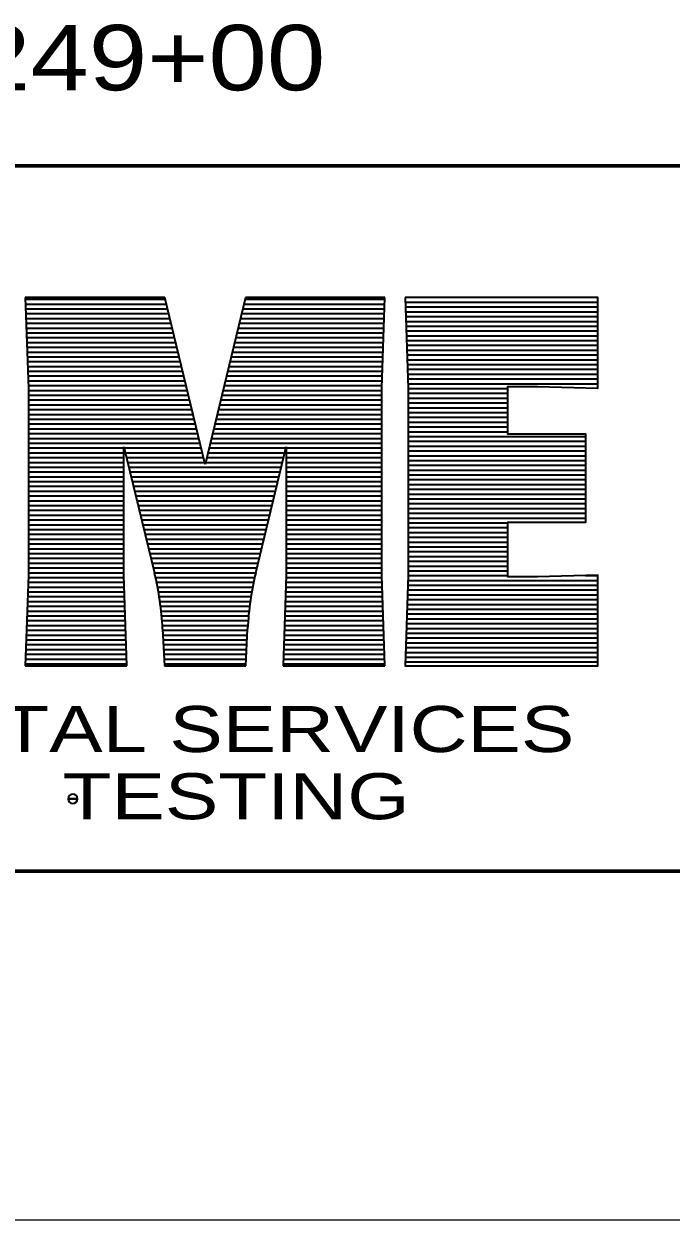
# Model space of a CAD drawing. Extents: x -76 to 974, y -1080 to -735.
# Drawn here: x 642.72 to 650.14, y -1056.11 to -1042.4 of the extents above; entities that cross this region are included whole.
import ezdxf
from ezdxf.enums import TextEntityAlignment as Align

# ---------------------------------------------------------------- set-up
doc = ezdxf.new("R2010")
doc.units = 0
doc.header["$LTSCALE"] = 0.36
doc.layers.add('63', color=7, linetype='Continuous', lineweight=35)

msp = doc.modelspace()

# ---------------------------------------------------------------- linework, layer by layer
at = {"layer": '63'}
for p, q in [((642.7326, -1045.5362), (642.7672, -1046.5743)), ((644.3305, -1045.5362), (642.7326, -1045.5362)), ((644.7933, -1047.4498), (644.3305, -1045.5362)), ((645.256, -1045.5362), (644.7933, -1047.4498)), ((646.8539, -1045.5362), (645.256, -1045.5362)), ((646.8193, -1046.5743), (646.8539, -1045.5362)), ((642.7332, -1045.5548), (644.335, -1045.5548)), ((642.7351, -1045.6098), (644.3483, -1045.6098)), ((642.7369, -1045.6648), (644.3616, -1045.6648)), ((645.2249, -1045.6648), (646.8496, -1045.6648)), ((645.2382, -1045.6098), (646.8514, -1045.6098)), ((645.2515, -1045.5548), (646.8533, -1045.5548)), ((647.0895, -1045.5883), (649.296, -1045.5883)), ((647.0913, -1045.6433), (649.296, -1045.6433)), ((642.7387, -1045.7198), (644.3749, -1045.7198)), ((642.7406, -1045.7748), (644.3882, -1045.7748)), ((645.1983, -1045.7748), (646.8459, -1045.7748)), ((645.2116, -1045.7198), (646.8478, -1045.7198)), ((647.0931, -1045.6983), (649.296, -1045.6983)), ((647.095, -1045.7533), (649.296, -1045.7533)), ((647.0968, -1045.8083), (649.296, -1045.8083)), ((642.7424, -1045.8298), (644.4015, -1045.8298)), ((642.7442, -1045.8848), (644.4148, -1045.8848)), ((642.7461, -1045.9398), (644.4281, -1045.9398)), ((645.1584, -1045.9398), (646.8404, -1045.9398)), ((645.1717, -1045.8848), (646.8423, -1045.8848)), ((645.185, -1045.8298), (646.8441, -1045.8298)), ((647.0986, -1045.8633), (649.296, -1045.8633)), ((647.1005, -1045.9183), (649.296, -1045.9183)), ((642.7479, -1045.9948), (644.4414, -1045.9948)), ((642.7497, -1046.0498), (644.4547, -1046.0498)), ((645.1318, -1046.0498), (646.8368, -1046.0498)), ((645.1451, -1045.9948), (646.8386, -1045.9948)), ((647.1023, -1045.9733), (649.296, -1045.9733)), ((647.1041, -1046.0283), (649.296, -1046.0283)), ((647.106, -1046.0833), (649.296, -1046.0833)), ((642.7516, -1046.1048), (644.468, -1046.1048)), ((642.7534, -1046.1598), (644.4813, -1046.1598)), ((642.7552, -1046.2148), (644.4946, -1046.2148)), ((645.0919, -1046.2148), (646.8313, -1046.2148)), ((645.1052, -1046.1598), (646.8331, -1046.1598)), ((645.1185, -1046.1048), (646.8349, -1046.1048)), ((647.1078, -1046.1383), (649.296, -1046.1383)), ((647.1096, -1046.1933), (649.296, -1046.1933)), ((642.7571, -1046.2698), (644.5079, -1046.2698)), ((642.7589, -1046.3248), (644.5212, -1046.3248)), ((645.0653, -1046.3248), (646.8276, -1046.3248)), ((645.0786, -1046.2698), (646.8294, -1046.2698)), ((647.1115, -1046.2483), (649.296, -1046.2483)), ((647.1133, -1046.3033), (649.296, -1046.3033)), ((647.1151, -1046.3583), (649.296, -1046.3583)), ((642.7607, -1046.3798), (644.5345, -1046.3798)), ((642.7626, -1046.4348), (644.5478, -1046.4348)), ((642.7644, -1046.4898), (644.5611, -1046.4898)), ((645.0254, -1046.4898), (646.8221, -1046.4898)), ((645.0387, -1046.4348), (646.8239, -1046.4348)), ((645.052, -1046.3798), (646.8258, -1046.3798)), ((647.117, -1046.4133), (649.296, -1046.4133)), ((647.1188, -1046.4683), (649.296, -1046.4683)), ((642.7662, -1046.5448), (644.5744, -1046.5448)), ((642.7672, -1046.5743), (642.7672, -1048.7197)), ((642.7672, -1046.5998), (644.5877, -1046.5998)), ((644.9988, -1046.5998), (646.8193, -1046.5998)), ((645.0121, -1046.5448), (646.8203, -1046.5448)), ((646.8193, -1048.7197), (646.8193, -1046.5743)), ((647.1206, -1046.5233), (649.296, -1046.5233)), ((647.1223, -1046.5783), (648.2643, -1046.5783)), ((647.1223, -1046.6333), (648.2643, -1046.6333)), ((642.7672, -1046.6548), (644.601, -1046.6548)), ((642.7672, -1046.7098), (644.6143, -1046.7098)), ((642.7672, -1046.7648), (644.6276, -1046.7648)), ((644.9589, -1046.7648), (646.8193, -1046.7648)), ((644.9722, -1046.7098), (646.8193, -1046.7098)), ((644.9855, -1046.6548), (646.8193, -1046.6548)), ((647.1223, -1046.6883), (648.2643, -1046.6883)), ((647.1223, -1046.7433), (648.2643, -1046.7433)), ((642.7672, -1046.8198), (644.6409, -1046.8198)), ((642.7672, -1046.8748), (644.6542, -1046.8748)), ((644.9323, -1046.8748), (646.8193, -1046.8748)), ((644.9456, -1046.8198), (646.8193, -1046.8198)), ((647.1223, -1046.7983), (648.2643, -1046.7983)), ((647.1223, -1046.8533), (648.2643, -1046.8533)), ((647.1223, -1046.9083), (648.2643, -1046.9083)), ((642.7672, -1046.9298), (644.6675, -1046.9298)), ((642.7672, -1046.9848), (644.6808, -1046.9848)), ((642.7672, -1047.0398), (644.6941, -1047.0398)), ((644.8924, -1047.0398), (646.8193, -1047.0398)), ((644.9057, -1046.9848), (646.8193, -1046.9848)), ((644.919, -1046.9298), (646.8193, -1046.9298)), ((647.1223, -1046.9633), (648.2643, -1046.9633)), ((647.1223, -1047.0183), (648.2643, -1047.0183)), ((642.7672, -1047.0948), (644.7074, -1047.0948)), ((642.7672, -1047.1498), (644.7207, -1047.1498)), ((644.8658, -1047.1498), (646.8193, -1047.1498)), ((644.8791, -1047.0948), (646.8193, -1047.0948)), ((647.1223, -1047.0733), (648.2643, -1047.0733)), ((647.1223, -1047.1283), (649.1571, -1047.1283)), ((647.1223, -1047.1833), (649.1571, -1047.1833)), ((642.7672, -1047.2048), (644.734, -1047.2048)), ((642.7672, -1047.2598), (643.8634, -1047.2598)), ((642.7672, -1047.3148), (643.8634, -1047.3148)), ((643.8634, -1047.2459), (644.2127, -1048.6901)), ((643.8634, -1048.7197), (643.8634, -1047.2459)), ((643.8668, -1047.2598), (644.7473, -1047.2598)), ((643.8801, -1047.3148), (644.7606, -1047.3148)), ((644.8259, -1047.3148), (645.7064, -1047.3148)), ((644.8392, -1047.2598), (645.7197, -1047.2598)), ((644.8525, -1047.2048), (646.8193, -1047.2048)), ((645.3738, -1048.6901), (645.7231, -1047.2459)), ((645.7231, -1047.2459), (645.7231, -1048.7197)), ((645.7231, -1047.2598), (646.8193, -1047.2598)), ((645.7231, -1047.3148), (646.8193, -1047.3148)), ((647.1223, -1047.2383), (649.1571, -1047.2383)), ((647.1223, -1047.2933), (649.1571, -1047.2933)), ((642.7672, -1047.3698), (643.8634, -1047.3698)), ((642.7672, -1047.4248), (643.8634, -1047.4248)), ((643.8934, -1047.3698), (644.7739, -1047.3698)), ((643.9067, -1047.4248), (644.7872, -1047.4248)), ((644.7993, -1047.4248), (645.6798, -1047.4248)), ((644.8126, -1047.3698), (645.6931, -1047.3698)), ((645.7231, -1047.3698), (646.8193, -1047.3698)), ((645.7231, -1047.4248), (646.8193, -1047.4248)), ((647.1223, -1047.3483), (649.1571, -1047.3483)), ((647.1223, -1047.4033), (649.1571, -1047.4033)), ((647.1223, -1047.4583), (649.1571, -1047.4583)), ((642.7672, -1047.4798), (643.8634, -1047.4798)), ((642.7672, -1047.5348), (643.8634, -1047.5348)), ((642.7672, -1047.5898), (643.8634, -1047.5898)), ((643.92, -1047.4798), (645.6665, -1047.4798)), ((643.9333, -1047.5348), (645.6532, -1047.5348)), ((643.9466, -1047.5898), (645.6399, -1047.5898)), ((645.7231, -1047.4798), (646.8193, -1047.4798)), ((645.7231, -1047.5348), (646.8193, -1047.5348)), ((645.7231, -1047.5898), (646.8193, -1047.5898)), ((647.1223, -1047.5133), (649.1571, -1047.5133)), ((647.1223, -1047.5683), (649.1571, -1047.5683)), ((642.7672, -1047.6448), (643.8634, -1047.6448)), ((642.7672, -1047.6998), (643.8634, -1047.6998)), ((643.9599, -1047.6448), (645.6266, -1047.6448)), ((643.9732, -1047.6998), (645.6133, -1047.6998)), ((645.7231, -1047.6448), (646.8193, -1047.6448)), ((645.7231, -1047.6998), (646.8193, -1047.6998)), ((647.1223, -1047.6233), (649.1571, -1047.6233)), ((647.1223, -1047.6783), (649.1571, -1047.6783)), ((647.1223, -1047.7333), (649.1571, -1047.7333)), ((642.7672, -1047.7548), (643.8634, -1047.7548)), ((642.7672, -1047.8098), (643.8634, -1047.8098)), ((642.7672, -1047.8648), (643.8634, -1047.8648)), ((643.9865, -1047.7548), (645.6, -1047.7548)), ((643.9998, -1047.8098), (645.5867, -1047.8098)), ((644.0131, -1047.8648), (645.5734, -1047.8648)), ((645.7231, -1047.7548), (646.8193, -1047.7548)), ((645.7231, -1047.8098), (646.8193, -1047.8098)), ((645.7231, -1047.8648), (646.8193, -1047.8648)), ((647.1223, -1047.7883), (649.1571, -1047.7883)), ((647.1223, -1047.8433), (649.1571, -1047.8433)), ((642.7672, -1047.9198), (643.8634, -1047.9198)), ((642.7672, -1047.9748), (643.8634, -1047.9748)), ((644.0264, -1047.9198), (645.5601, -1047.9198)), ((644.0397, -1047.9748), (645.5468, -1047.9748)), ((645.7231, -1047.9198), (646.8193, -1047.9198)), ((645.7231, -1047.9748), (646.8193, -1047.9748)), ((647.1223, -1047.8983), (649.1571, -1047.8983)), ((647.1223, -1047.9533), (649.1571, -1047.9533)), ((647.1223, -1048.0083), (649.1571, -1048.0083)), ((642.7672, -1048.0298), (643.8634, -1048.0298)), ((642.7672, -1048.0848), (643.8634, -1048.0848)), ((642.7672, -1048.1398), (643.8634, -1048.1398)), ((644.053, -1048.0298), (645.5335, -1048.0298)), ((644.0663, -1048.0848), (645.5202, -1048.0848)), ((644.0796, -1048.1398), (645.5069, -1048.1398)), ((645.7231, -1048.0298), (646.8193, -1048.0298)), ((645.7231, -1048.0848), (646.8193, -1048.0848)), ((645.7231, -1048.1398), (646.8193, -1048.1398)), ((647.1223, -1048.0633), (649.1571, -1048.0633)), ((647.1223, -1048.1183), (648.2643, -1048.1183)), ((642.7672, -1048.1948), (643.8634, -1048.1948)), ((642.7672, -1048.2498), (643.8634, -1048.2498)), ((644.0929, -1048.1948), (645.4936, -1048.1948)), ((644.1062, -1048.2498), (645.4803, -1048.2498)), ((645.7231, -1048.1948), (646.8193, -1048.1948)), ((645.7231, -1048.2498), (646.8193, -1048.2498)), ((647.1223, -1048.1733), (648.2643, -1048.1733)), ((647.1223, -1048.2283), (648.2643, -1048.2283)), ((647.1223, -1048.2833), (648.2643, -1048.2833)), ((642.7672, -1048.3048), (643.8634, -1048.3048)), ((642.7672, -1048.3598), (643.8634, -1048.3598)), ((642.7672, -1048.4148), (643.8634, -1048.4148)), ((644.1195, -1048.3048), (645.467, -1048.3048)), ((644.1328, -1048.3598), (645.4537, -1048.3598)), ((644.1461, -1048.4148), (645.4404, -1048.4148)), ((645.7231, -1048.3048), (646.8193, -1048.3048)), ((645.7231, -1048.3598), (646.8193, -1048.3598)), ((645.7231, -1048.4148), (646.8193, -1048.4148)), ((647.1223, -1048.3383), (648.2643, -1048.3383)), ((647.1223, -1048.3933), (648.2643, -1048.3933)), ((642.7672, -1048.4698), (643.8634, -1048.4698)), ((642.7672, -1048.5248), (643.8634, -1048.5248)), ((644.1594, -1048.4698), (645.4271, -1048.4698)), ((644.1727, -1048.5248), (645.4138, -1048.5248)), ((645.7231, -1048.4698), (646.8193, -1048.4698)), ((645.7231, -1048.5248), (646.8193, -1048.5248)), ((647.1223, -1048.4483), (648.2643, -1048.4483)), ((647.1223, -1048.5033), (648.2643, -1048.5033)), ((647.1223, -1048.5583), (648.2643, -1048.5583)), ((642.7672, -1048.5798), (643.8634, -1048.5798)), ((642.7672, -1048.6348), (643.8634, -1048.6348)), ((642.7672, -1048.6898), (643.8634, -1048.6898)), ((644.186, -1048.5798), (645.4005, -1048.5798)), ((644.1993, -1048.6348), (645.3872, -1048.6348)), ((644.2126, -1048.6898), (645.3739, -1048.6898)), ((645.7231, -1048.5798), (646.8193, -1048.5798)), ((645.7231, -1048.6348), (646.8193, -1048.6348)), ((645.7231, -1048.6898), (646.8193, -1048.6898)), ((647.1223, -1048.6133), (648.2643, -1048.6133)), ((647.1223, -1048.6683), (648.2643, -1048.6683)), ((642.7672, -1048.7197), (642.7326, -1049.7578)), ((642.7646, -1048.7998), (643.8661, -1048.7998)), ((642.7664, -1048.7448), (643.8643, -1048.7448)), ((643.898, -1049.7578), (643.8634, -1048.7197)), ((644.2255, -1048.7448), (645.361, -1048.7448)), ((644.2374, -1048.7998), (645.3492, -1048.7998)), ((645.7231, -1048.7197), (645.6885, -1049.7578)), ((645.7204, -1048.7998), (646.822, -1048.7998)), ((645.7222, -1048.7448), (646.8201, -1048.7448)), ((646.8539, -1049.7578), (646.8193, -1048.7197)), ((647.1186, -1048.8333), (649.296, -1048.8333)), ((647.1204, -1048.7783), (649.296, -1048.7783)), ((647.1222, -1048.7233), (648.2643, -1048.7233)), ((649.1531, -1048.7233), (649.296, -1048.7233)), ((642.7591, -1048.9648), (643.8716, -1048.9648)), ((642.7609, -1048.9098), (643.8698, -1048.9098)), ((642.7627, -1048.8548), (643.8679, -1048.8548)), ((644.2483, -1048.8548), (645.3382, -1048.8548)), ((644.2584, -1048.9098), (645.3282, -1048.9098)), ((644.2675, -1048.9648), (645.319, -1048.9648)), ((645.7149, -1048.9648), (646.8275, -1048.9648)), ((645.7167, -1048.9098), (646.8256, -1048.9098)), ((645.7186, -1048.8548), (646.8238, -1048.8548)), ((647.1149, -1048.9433), (649.296, -1048.9433)), ((647.1167, -1048.8883), (649.296, -1048.8883)), ((642.7554, -1049.0748), (643.8753, -1049.0748)), ((642.7572, -1049.0198), (643.8734, -1049.0198)), ((644.2757, -1049.0198), (645.3108, -1049.0198)), ((644.283, -1049.0748), (645.3035, -1049.0748)), ((645.7112, -1049.0748), (646.8311, -1049.0748)), ((645.7131, -1049.0198), (646.8293, -1049.0198)), ((647.1094, -1049.1083), (649.296, -1049.1083)), ((647.1112, -1049.0533), (649.296, -1049.0533)), ((647.1131, -1048.9983), (649.296, -1048.9983)), ((642.7499, -1049.2398), (643.8808, -1049.2398)), ((642.7517, -1049.1848), (643.8789, -1049.1848)), ((642.7536, -1049.1298), (643.8771, -1049.1298)), ((644.2894, -1049.1298), (645.2971, -1049.1298)), ((644.295, -1049.1848), (645.2916, -1049.1848)), ((644.2996, -1049.2398), (645.2869, -1049.2398)), ((645.7057, -1049.2398), (646.8366, -1049.2398)), ((645.7076, -1049.1848), (646.8348, -1049.1848)), ((645.7094, -1049.1298), (646.833, -1049.1298)), ((647.1057, -1049.2183), (649.296, -1049.2183)), ((647.1076, -1049.1633), (649.296, -1049.1633)), ((642.7462, -1049.3498), (643.8844, -1049.3498)), ((642.7481, -1049.2948), (643.8826, -1049.2948)), ((644.3034, -1049.2948), (645.2831, -1049.2948)), ((644.3055, -1049.3342), (644.3263, -1049.7578)), ((644.3063, -1049.3498), (645.2802, -1049.3498)), ((645.2602, -1049.7578), (645.281, -1049.3342)), ((645.7021, -1049.3498), (646.8403, -1049.3498)), ((645.7039, -1049.2948), (646.8385, -1049.2948)), ((647.1002, -1049.3833), (649.296, -1049.3833)), ((647.1021, -1049.3283), (649.296, -1049.3283)), ((647.1039, -1049.2733), (649.296, -1049.2733)), ((642.7407, -1049.5148), (643.8899, -1049.5148)), ((642.7426, -1049.4598), (643.8881, -1049.4598)), ((642.7444, -1049.4048), (643.8863, -1049.4048)), ((644.309, -1049.4048), (645.2775, -1049.4048)), ((644.3117, -1049.4598), (645.2748, -1049.4598)), ((644.3144, -1049.5148), (645.2721, -1049.5148)), ((645.6966, -1049.5148), (646.8458, -1049.5148)), ((645.6984, -1049.4598), (646.844, -1049.4598)), ((645.7002, -1049.4048), (646.8421, -1049.4048)), ((647.0966, -1049.4933), (649.296, -1049.4933)), ((647.0984, -1049.4383), (649.296, -1049.4383)), ((642.7371, -1049.6248), (643.8936, -1049.6248)), ((642.7389, -1049.5698), (643.8918, -1049.5698)), ((644.3171, -1049.5698), (645.2695, -1049.5698)), ((644.3197, -1049.6248), (645.2668, -1049.6248)), ((645.6929, -1049.6248), (646.8495, -1049.6248)), ((645.6947, -1049.5698), (646.8476, -1049.5698)), ((647.0911, -1049.6583), (649.296, -1049.6583)), ((647.0929, -1049.6033), (649.296, -1049.6033)), ((647.0947, -1049.5483), (649.296, -1049.5483)), ((642.7326, -1049.7578), (643.898, -1049.7578)), ((642.7334, -1049.7348), (643.8973, -1049.7348)), ((642.7352, -1049.6798), (643.8954, -1049.6798)), ((644.3224, -1049.6798), (645.2641, -1049.6798)), ((644.3251, -1049.7348), (645.2614, -1049.7348)), ((644.3263, -1049.7578), (645.2602, -1049.7578)), ((645.6885, -1049.7578), (646.8539, -1049.7578)), ((645.6892, -1049.7348), (646.8531, -1049.7348)), ((645.6911, -1049.6798), (646.8513, -1049.6798)), ((647.0892, -1049.7133), (649.296, -1049.7133)), ((643.2761, -1051.2815), (643.2226, -1051.2815)), ((643.2226, -1051.2815), (643.2761, -1051.2815)), ((643.3296, -1051.2815), (643.2762, -1051.2815)), ((643.2762, -1051.2815), (643.3296, -1051.2815)), ((583.1701, -1052.1123), (683.1701, -1052.1123))]:
    msp.add_line(p, q, dxfattribs=at)
at = {"layer": '63', "lineweight": 13}
msp.add_line((688.1701, -1056.1123), (578.1701, -1056.1123), dxfattribs=at)
at = {"layer": '63', "lineweight": 60}
msp.add_lwpolyline([(583.1701, -1044.0258), (683.1701, -1044.0258), (683.1701, -1052.1123), (583.1701, -1052.1123)], close=True, dxfattribs=at)
at = {"layer": '63'}
msp.add_lwpolyline([(647.0877, -1045.5362), (647.1223, -1046.5743), (647.1223, -1047.6065), (647.1223, -1048.7197), (647.0877, -1049.7578), (649.296, -1049.7578), (649.296, -1048.7197), (648.6039, -1048.737), (648.2643, -1048.737), (648.2643, -1048.1116), (649.1571, -1048.1116), (649.1571, -1047.6065), (649.1571, -1047.1014), (648.2643, -1047.1014), (648.2643, -1046.557), (648.6039, -1046.557), (649.296, -1046.5743), (649.296, -1045.5362)], close=True, dxfattribs=at)
for centre, radius, start, end in [((640.8492, -1049.5035), 3.4604, 2.80418, 13.59498), ((648.7373, -1049.5035), 3.4604, 166.40502, 177.19582), ((643.2761, -1051.2815), 0.0535, 0, 180), ((643.2761, -1051.2815), 0.0535, 180, 0), ((643.2761, -1051.2815), 0.00005, 0, 180), ((643.2761, -1051.2815), 0.00005, 180, 0)]:
    msp.add_arc(centre, radius, start, end, dxfattribs=at)

# ---------------------------------------------------------------- texts
at = {"layer": '63', "width": 1.2}
msp.add_text('249+00', height=0.75, dxfattribs=at).set_placement((644.1467, -1043.1595), align=Align.CENTER)
at = {"layer": '63', "width": 1.3}
for s, p in [('ENVIRONMENTAL SERVICES', (636.224, -1050.7461)), ('ENGINEERING  TESTING', (636.224, -1051.5167))]:
    msp.add_text(s, height=0.528, dxfattribs=at).set_placement(p)

doc.saveas('drawing.dxf')
